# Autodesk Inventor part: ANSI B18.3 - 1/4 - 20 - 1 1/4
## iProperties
Comments: To add or edit properties for Autodesk Inventor files, use iProperties.
Created: 2005-06
Part Number: ANSI B18.3 - 1/4 - 20 - 1 1/4
Vendor: Autodesk Inc.
Document SubType Name: Modeling
Designer: John Blackburn
Material: Default
Description: Hexagon Socket Head Cap Screw
Standard: ANSI B18.3
Alert: To add or edit properties for Autodesk Inventor files, use iProperties.
Control State: 0
Master: False
Checked Out: False
Shininess: 64.0
Length Units: 11272
Angle Units: 11279
Time Units: 11290
Mass Units: 11286
Length Display Precision: 3
Angle Display Precision: 2
Compacted: True
EGR: 3
Classification: un/spsc 31161501
Density: 0.0
Volumn: 0.0
Area: 0.0
PropertySet Name: Model Information
Author: John Blackburn
Revision Number: 8
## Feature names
1. Body [Revolution]
2. Slot [Extrusion]
3. Fillet1
4. Chamfer1
